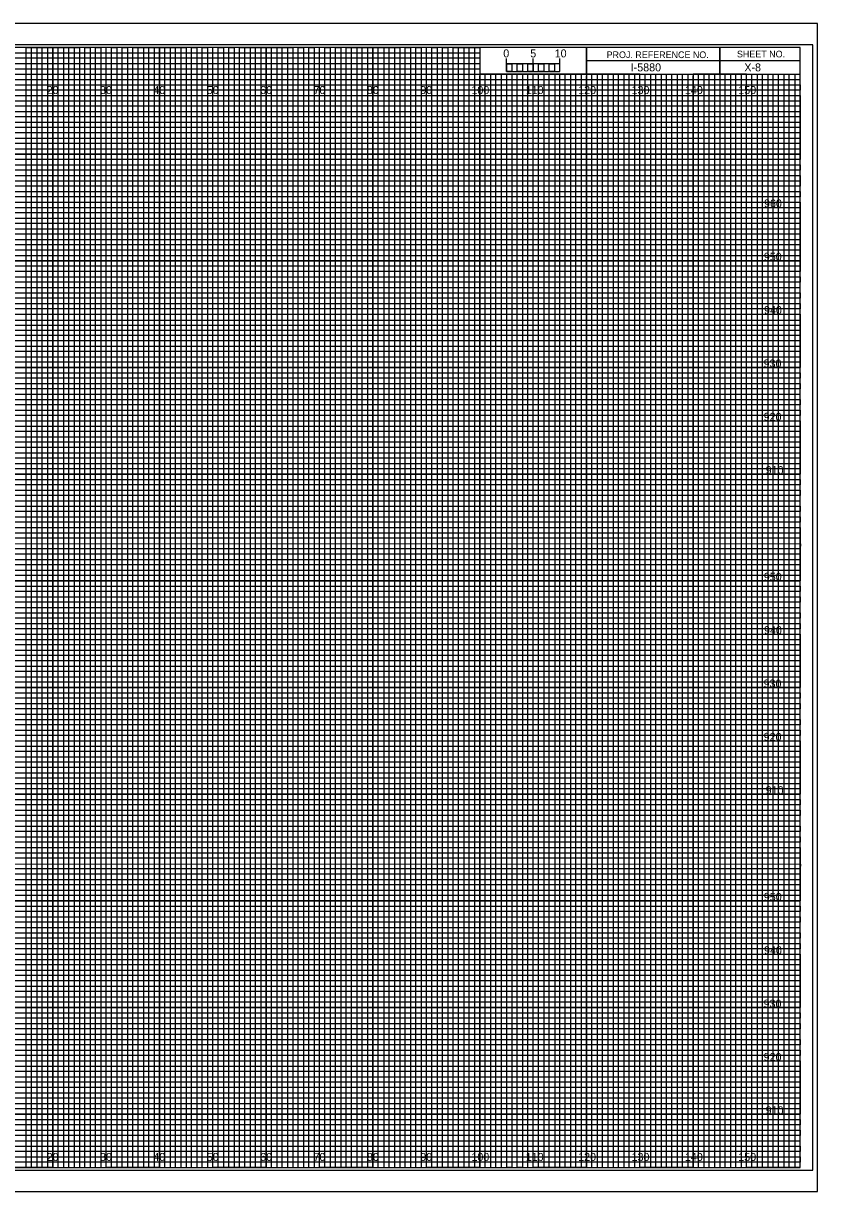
# Model space of a CAD drawing. Extents: x -13 to 323, y -4 to 3074.
# Drawn here: x 174.5 to 323.3, y 1315.5 to 1534.5 of the extents above; entities that cross this region are included whole.
import ezdxf

# ---------------------------------------------------------------- set-up
doc = ezdxf.new("R2010")
doc.units = 0
for name, color, linetype in [('Prop XS Bar Scale Labels', 7, 'Continuous'), ('Prop XS Elevation Labels', 7, 'Continuous'), ('Prop XS Offset Labels', 7, 'Continuous'), ('Prop XS Project Number', 7, 'Continuous'), ('Prop XS Sheet Number', 7, 'Continuous'), ('Sheet Cross Section CELL', 7, 'Continuous'), ('Sheet Cross Section Grid Major CELL', 7, 'Continuous'), ('Sheet Cross Section Grid Middle CELL', 7, 'Continuous'), ('Sheet Cross Section Grid Minor 1 CELL', 7, 'Continuous'), ('Sheet Cross Section Grid Minor 2 CELL', 7, 'Continuous'), ('Sheet Cross Section Scale CELL', 7, 'Continuous'), ('Sheet Cutting Line CELL', 7, 'Continuous'), ('Sheet DOT Grid CELL', 7, 'Continuous'), ('Sheet Plot Border Inside CELL', 7, 'Continuous'), ('Sheet Plot Border Outside CELL', 7, 'Continuous')]:
    doc.layers.add(name, color=color, linetype=linetype)

msp = doc.modelspace()

# ---------------------------------------------------------------- linework, layer by layer
at = {"layer": 'Sheet Cross Section CELL'}
for p, q in [((305, 1530), (305, 1525)), ((305, 1525), (305, 1530)), ((280, 1527.5), (280, 1525)), ((320, 1527.49), (280, 1527.49)), ((280, 1525), (320, 1525))]:
    msp.add_line(p, q, dxfattribs=at)
for points in [[(320, 1530), (0, 1530), (0, 1320), (320, 1320)], [(280, 1530), (260, 1530), (260, 1525.03), (280, 1525.03)], [(320, 1530), (280, 1530), (280, 1525), (320, 1525)]]:
    msp.add_lwpolyline(points, close=True, dxfattribs=at)
at = {"layer": 'Sheet Cross Section Grid Major CELL'}
for p, q in [((190, 1530), (180, 1530)), ((180, 1530), (180, 1320)), ((190, 1320), (190, 1530)), ((210, 1530), (200, 1530)), ((200, 1530), (200, 1320)), ((210, 1320), (210, 1530)), ((230, 1530), (220, 1530)), ((220, 1530), (220, 1320)), ((230, 1320), (230, 1530)), ((250, 1530), (240, 1530)), ((240, 1530), (240, 1320)), ((250, 1320), (250, 1530)), ((260, 1530), (260, 1320)), ((270, 1320), (270, 1525)), ((290, 1525), (280, 1525)), ((280, 1525), (280, 1320)), ((290, 1320), (290, 1525)), ((310, 1525), (300, 1525)), ((300, 1525), (300, 1320)), ((310, 1320), (310, 1525)), ((180, 1320), (170, 1320)), ((200, 1320), (190, 1320)), ((220, 1320), (210, 1320)), ((240, 1320), (230, 1320)), ((260, 1320), (250, 1320)), ((280, 1320), (270, 1320)), ((300, 1320), (290, 1320)), ((320, 1320), (310, 1320)), ((320, 1320), (320, 1320))]:
    msp.add_line(p, q, dxfattribs=at)
for points in [[(0, 1520), (320, 1520), (320, 1510), (0, 1510)], [(0, 1500), (320, 1500), (320, 1490), (0, 1490)], [(0, 1480), (320, 1480), (320, 1470), (0, 1470)], [(0, 1460), (320, 1460), (320, 1450), (0, 1450)], [(0, 1440), (320, 1440), (320, 1430), (0, 1430)], [(0, 1420), (320, 1420), (320, 1410), (0, 1410)], [(0, 1400), (320, 1400), (320, 1390), (0, 1390)], [(0, 1380), (320, 1380), (320, 1370), (0, 1370)], [(0, 1360), (320, 1360), (320, 1350), (0, 1350)], [(0, 1340), (320, 1340), (320, 1330), (0, 1330)]]:
    msp.add_lwpolyline(points, dxfattribs=at)
at = {"layer": 'Sheet Cross Section Grid Middle CELL'}
for points in [[(165, 1320), (175, 1320), (175, 1530), (185, 1530), (185, 1320), (195, 1320), (195, 1530), (205, 1530), (205, 1320), (215, 1320), (215, 1530), (225, 1530), (225, 1320), (235, 1320), (235, 1530), (245, 1530), (245, 1320), (255, 1320), (255, 1530), (259.93, 1530), (260, 1530), (260, 1525), (264.99, 1525), (264.99, 1320), (275, 1320), (275, 1525), (285, 1525), (285, 1320), (295, 1320), (295, 1525), (305, 1525), (305, 1320), (315, 1320), (315, 1525)], [(0, 1525), (275, 1525)], [(0, 1505), (320, 1505), (320, 1515), (0, 1515)], [(0, 1485), (320, 1485), (320, 1495), (0, 1495)], [(0, 1465), (320, 1465), (320, 1475), (0, 1475)], [(0, 1445), (320, 1445), (320, 1455), (0, 1455)], [(0, 1425), (320, 1425), (320, 1435), (0, 1435)], [(0, 1405), (320, 1405), (320, 1415), (0, 1415)], [(0, 1385), (320, 1385), (320, 1395), (0, 1395)], [(0, 1365), (320, 1365), (320, 1375), (0, 1375)], [(0, 1345), (320, 1345), (320, 1355), (0, 1355)], [(0, 1325), (320, 1325), (320, 1335), (0, 1335)]]:
    msp.add_lwpolyline(points, dxfattribs=at)
at = {"layer": 'Sheet Cross Section Grid Minor 1 CELL'}
for p, q in [((0, 1529), (260, 1529)), ((260, 1529), (260, 1527.98)), ((260, 1527.98), (0, 1527.98)), ((0, 1527), (260, 1527)), ((260, 1527), (260, 1525.89)), ((260, 1525.89), (0, 1525.89)), ((0, 1524), (320, 1524))]:
    msp.add_line(p, q, dxfattribs=at)
for points in [[(0, 1523), (270, 1523), (320, 1523), (320, 1522), (0, 1522)], [(0, 1521), (320, 1521), (320, 1519), (0, 1519)], [(0, 1518), (320, 1518), (320, 1517), (0, 1516.98)], [(0, 1516), (320, 1516), (320, 1514), (0, 1514)], [(0, 1513), (320, 1513), (320, 1512), (0, 1512)], [(0, 1511), (320, 1511), (320, 1509), (0, 1509)], [(0, 1508), (320, 1508), (320, 1507), (0, 1507)], [(0, 1506), (320, 1506), (320, 1504), (0, 1504)], [(0, 1503), (320, 1503), (320, 1502), (0, 1502)], [(0, 1501), (320, 1501), (320, 1499), (0, 1499)], [(0, 1498), (320, 1498), (320, 1497), (0, 1497)], [(0, 1496), (320, 1496), (320, 1493.95), (320, 1493), (320, 1492), (0, 1492)], [(0, 1494), (320, 1494), (320, 1493), (0, 1493)], [(0, 1491), (320, 1491), (320, 1489), (0, 1489.03)], [(0, 1489.03), (320, 1489), (320, 1488), (0, 1488)], [(0, 1487), (320, 1487), (320, 1486), (0, 1486)], [(0, 1484), (320, 1484), (320, 1483), (0, 1483)], [(0, 1482), (320, 1482), (320, 1481), (0, 1481)], [(-0.07, 1478.89), (320, 1478.89), (320, 1477.88), (-0.07, 1477.88)], [(0, 1477), (320, 1477), (320, 1476), (0, 1476)], [(0, 1474), (320, 1474), (320, 1473), (0, 1473)], [(0, 1472), (320, 1472), (320, 1471), (0, 1471)], [(0, 1469), (320, 1469), (320, 1468), (0, 1468)], [(0, 1467), (320, 1467), (320, 1466), (0, 1466)], [(0, 1464), (320, 1464), (320, 1463), (0, 1463)], [(0, 1462), (320, 1462), (320, 1461), (0, 1461)], [(0, 1459), (320, 1459), (319.99, 1457.98), (0, 1458)], [(0, 1457), (320, 1457), (320, 1456), (0, 1456)], [(0, 1454), (320, 1454), (320, 1453), (0, 1453)], [(0, 1452), (320, 1452), (320, 1451), (0, 1451)], [(0, 1449), (320, 1449), (320, 1448), (0, 1448)], [(0, 1447), (320, 1447), (320, 1446), (0, 1446)], [(0, 1444), (320, 1444), (320, 1443), (0, 1443)], [(0, 1442), (320, 1442), (320, 1441), (0, 1441)], [(0, 1439), (320, 1439), (320, 1438), (0, 1438)], [(0, 1436.99), (320.07, 1436.91), (320, 1436), (0, 1436)], [(0, 1434), (320, 1434), (320, 1433), (0, 1433)], [(0, 1432), (320, 1432), (320, 1431), (0, 1431)], [(0, 1429), (320, 1429), (320, 1428), (0, 1428)], [(0, 1427), (320, 1427), (320, 1426), (0, 1426)], [(0, 1424), (320, 1424), (320, 1423), (0, 1423)], [(0, 1422), (320, 1422), (320, 1421), (0, 1421)], [(0, 1419), (320, 1419), (320, 1418), (0, 1418)], [(0, 1417), (320, 1417), (320, 1416), (0, 1416)], [(0, 1414), (320, 1414), (320, 1413), (0, 1413)], [(0, 1412), (320, 1412), (320, 1411), (0, 1411)], [(0, 1409), (320, 1409), (320, 1408), (0, 1408)], [(0, 1407), (320, 1407), (320, 1406), (0, 1406)], [(0, 1404), (320, 1404), (320, 1403), (0, 1403)], [(0, 1402), (320, 1402), (320, 1401), (0, 1401)], [(0, 1399), (320, 1399), (319.99, 1397.98), (0, 1398)], [(0, 1397), (320, 1397), (320, 1396), (0, 1396)], [(0, 1394), (320, 1394), (320, 1393), (0, 1393)], [(0, 1392), (320, 1392), (320, 1391), (0, 1391)], [(0, 1389), (320, 1389), (320, 1388), (0, 1388)], [(0, 1387), (320, 1387), (320, 1386), (0, 1386)], [(0, 1384), (320, 1384), (320, 1383), (0, 1383)], [(0, 1382), (320, 1382), (320, 1381), (0, 1381)], [(0, 1379), (320, 1379), (320, 1378), (0, 1378)], [(0, 1376.99), (320.07, 1376.91), (320, 1376), (0, 1376)], [(0, 1374), (320, 1374), (320, 1373), (0, 1373)], [(0, 1372), (320, 1372), (320, 1371), (0, 1371)], [(0, 1369), (320, 1369), (320, 1368), (0, 1368)], [(0, 1367), (320, 1367), (320, 1366), (0, 1366)], [(0, 1364), (320, 1364), (320, 1363), (0, 1363)], [(0, 1362), (320, 1362), (320, 1361), (0, 1361)], [(0, 1359), (320, 1359), (320, 1358), (0, 1358)], [(0, 1357), (320, 1357), (320, 1356), (0, 1356)], [(0, 1354), (320, 1354), (320, 1353), (0, 1353)], [(0, 1352), (320, 1352), (320, 1351), (0, 1351)], [(0, 1349), (320, 1349), (320, 1348), (0, 1348)], [(0, 1347), (320, 1347), (320, 1346), (0, 1346)], [(0, 1344), (320, 1344), (320, 1343), (0, 1343)], [(0, 1342), (320, 1342), (320, 1341), (0, 1341)], [(0, 1339), (320, 1339), (320, 1338), (0, 1338)], [(0, 1337), (320, 1337), (320, 1336), (0, 1336)], [(0, 1334), (320, 1334), (320, 1333), (0, 1333)], [(0, 1332), (320, 1332), (320, 1331), (0, 1331)], [(0, 1329), (320, 1329), (320, 1328), (0, 1328)], [(0, 1327), (320, 1327), (320, 1326), (0, 1326)], [(0, 1324), (320, 1324), (320, 1323), (0, 1323)], [(0, 1322), (320, 1322), (320, 1321), (0, 1321)]]:
    msp.add_lwpolyline(points, dxfattribs=at)
at = {"layer": 'Sheet Cross Section Grid Minor 2 CELL'}
for p, q in [((267, 1525), (266.01, 1525)), ((266.01, 1525), (266.01, 1320)), ((267, 1320), (267, 1525)), ((269, 1525), (268, 1525)), ((268, 1525), (268, 1320)), ((269, 1320), (269, 1525)), ((266.01, 1320), (265, 1320)), ((268, 1320), (267, 1320))]:
    msp.add_line(p, q, dxfattribs=at)
for points in [[(175, 1320), (176, 1320), (176, 1530), (177, 1530), (177, 1320)], [(177, 1320), (178, 1320), (178, 1530), (179, 1530), (179, 1320)], [(180, 1320), (181, 1320), (181, 1530), (182, 1530), (182, 1320)], [(182, 1320), (183, 1320), (183, 1530), (184, 1530), (184, 1320)], [(185, 1320), (186, 1320), (186, 1530), (187, 1530), (187, 1320)], [(187, 1320), (188, 1320), (188, 1530), (189, 1530), (189, 1320)], [(190, 1320), (191, 1320), (191, 1530), (192, 1530), (192, 1320)], [(192, 1320), (193, 1320), (193, 1530), (194, 1530), (194, 1320)], [(195, 1320), (196, 1320), (196, 1530), (197, 1530), (197, 1320)], [(197, 1320), (198, 1320), (198, 1530), (199, 1530), (199, 1320)], [(200, 1320), (201, 1320), (201, 1530), (202, 1530), (202, 1320)], [(202, 1320), (203, 1320), (203, 1530), (204, 1530), (204, 1320)], [(205, 1320), (206, 1320), (206, 1530), (207, 1530), (207, 1320)], [(207, 1320), (208, 1320), (208, 1530), (209, 1530), (209, 1320)], [(210, 1320), (211, 1320), (211, 1530), (212, 1530), (212, 1320)], [(212, 1320), (213, 1320), (213, 1530), (214, 1530), (214, 1320)], [(215, 1320), (216, 1320), (216, 1530), (217, 1530), (217, 1320)], [(217, 1320), (218, 1320), (218, 1530), (219, 1530), (219, 1320)], [(220, 1320), (221, 1320), (221, 1530), (222, 1530), (222, 1320)], [(222, 1320), (223, 1320), (223, 1530), (224, 1530), (224, 1320)], [(225, 1320), (226, 1320), (226, 1530), (227, 1530), (227, 1320)], [(227, 1320), (228, 1320), (228, 1530), (229, 1530), (229, 1320)], [(230, 1320), (231, 1320), (231, 1530), (232, 1530), (232, 1320)], [(232, 1320), (233, 1320), (233, 1530), (234, 1530), (234, 1320)], [(235, 1320), (236, 1320), (236, 1530), (237, 1530), (237, 1320)], [(237, 1320), (238, 1320), (238, 1530), (239, 1530), (239, 1320)], [(240, 1320), (241, 1320), (241, 1530), (242, 1530), (242, 1320)], [(242, 1320), (243, 1320), (243, 1530), (244, 1530), (244, 1320)], [(245, 1320), (246, 1320), (246, 1530), (247, 1530), (247, 1320)], [(247, 1320), (248, 1320), (248, 1530), (249, 1530), (249, 1320)], [(250, 1320), (251, 1320), (251, 1530), (252, 1530), (252, 1320)], [(252, 1320), (253, 1320), (253, 1530), (254, 1530), (254, 1320)], [(255, 1320), (256, 1320), (256, 1530), (257, 1530), (257, 1320)], [(257, 1320), (258, 1320), (258, 1530), (259, 1530), (259, 1320)], [(260, 1320), (261, 1320), (261, 1525), (262.02, 1525), (262.02, 1320)], [(262, 1320), (263, 1320), (263, 1525), (263.99, 1525), (263.99, 1320)], [(270, 1320), (270.98, 1320), (270.98, 1525), (272, 1525), (272, 1320)], [(272, 1320), (273, 1320), (273, 1525), (274.05, 1525), (274.05, 1320)], [(275, 1320), (276, 1320), (276, 1525), (277, 1525), (277, 1320)], [(277, 1320), (278, 1320), (278, 1525), (279, 1525), (279, 1320)], [(280, 1320), (281, 1320), (281, 1525), (282, 1525), (282, 1320)], [(282, 1320), (283, 1320), (283, 1525), (284, 1525), (284, 1320)], [(285, 1320), (286, 1320), (286, 1525), (287, 1525), (287, 1320)], [(287, 1320), (288, 1320), (288, 1525), (289, 1525), (289, 1320)], [(290, 1320), (291, 1320), (291, 1525), (292, 1525), (292, 1320)], [(292, 1320), (293, 1320), (293, 1525), (294, 1525), (294, 1320)], [(295, 1320), (296, 1320), (296, 1525), (297, 1525), (297, 1320)], [(297, 1320), (298, 1320), (298, 1525), (299, 1525), (299, 1320)], [(300, 1320), (301, 1320), (301, 1525), (302, 1525), (302, 1320)], [(302, 1320), (303, 1320), (303, 1525), (304, 1525), (304, 1320)], [(305, 1320), (306, 1320), (306, 1525), (307, 1525), (307, 1320)], [(307, 1320), (308, 1320), (308, 1525), (309, 1525), (309, 1320)], [(310, 1320), (311, 1320), (311, 1525), (312, 1525), (312, 1320)], [(312, 1320), (313, 1320), (313, 1525), (314, 1525), (314, 1320)], [(315, 1320), (316, 1320), (316, 1525), (317, 1525), (317, 1320)], [(317, 1320), (318, 1320), (318, 1525), (319, 1525), (319, 1320)]]:
    msp.add_lwpolyline(points, dxfattribs=at)
at = {"layer": 'Sheet Cross Section Scale CELL'}
for p, q in [((265, 1525.49), (265, 1527.9)), ((265, 1526.9), (265, 1527.9)), ((270, 1525.49), (270, 1527.9)), ((275, 1525.49), (275, 1527.9)), ((275, 1526.9), (275, 1527.9))]:
    msp.add_line(p, q, dxfattribs=at)
for points in [[(275, 1526.9), (265, 1526.9), (265, 1525.49), (275, 1525.49)], [(265, 1526.9), (266, 1526.9), (266, 1525.49), (265, 1525.49)], [(267, 1526.9), (268, 1526.9), (268, 1525.49), (267, 1525.49)], [(269, 1526.9), (270, 1526.9), (270, 1525.49), (269, 1525.49)], [(271, 1526.9), (272, 1526.9), (272, 1525.49), (271, 1525.49)], [(273, 1526.9), (274, 1526.9), (274, 1525.49), (273, 1525.49)]]:
    msp.add_lwpolyline(points, close=True, dxfattribs=at)
at = {"layer": 'Sheet Cutting Line CELL'}
for p, q in [((323.3, 1534.5), (-13.4, 1534.5)), ((-13.4, 1315.5), (323.3, 1315.5))]:
    msp.add_line(p, q, dxfattribs=at)
at = {"layer": 'Sheet DOT Grid CELL'}
for p, q in [((180, 1320), (180, 1530)), ((190, 1320), (190, 1530)), ((200, 1320), (200, 1530)), ((210, 1320), (210, 1530)), ((220, 1320), (220, 1530)), ((230, 1320), (230, 1530)), ((240, 1320), (240, 1530)), ((250, 1320), (250, 1530)), ((260, 1320), (260, 1524.69)), ((270, 1320), (270, 1524.69)), ((280, 1320), (280, 1524.69)), ((290, 1320), (290, 1524.69)), ((300, 1320), (300, 1524.69)), ((310, 1320), (310, 1524.69)), ((0, 1520), (320, 1520)), ((0, 1510), (320, 1510)), ((0, 1500), (320, 1500)), ((0, 1490), (320, 1490)), ((0, 1480), (320, 1480)), ((0, 1470), (320, 1470)), ((0, 1460), (320, 1460)), ((0, 1450), (320, 1450)), ((0, 1440), (320, 1440)), ((0, 1430), (320, 1430)), ((0, 1420), (320, 1420)), ((0, 1410), (320, 1410)), ((0, 1400), (320, 1400)), ((0, 1390), (320, 1390)), ((0, 1380), (320, 1380)), ((0, 1370), (320, 1370)), ((0, 1360), (320, 1360)), ((0, 1350), (320, 1350)), ((0, 1340), (320, 1340)), ((0, 1330), (320, 1330))]:
    msp.add_line(p, q, dxfattribs=at)
at = {"layer": 'Sheet Plot Border Inside CELL'}
msp.add_lwpolyline([(-10.8, 1319.5), (322.4, 1319.5), (322.4, 1530.5), (-10.8, 1530.5)], close=True, dxfattribs=at)
at = {"layer": 'Sheet Plot Border Outside CELL'}
msp.add_lwpolyline([(-13.4, 1315.5), (323.3, 1315.5), (323.3, 1534.5), (-13.4, 1534.5)], close=True, dxfattribs=at)

# ---------------------------------------------------------------- texts
at = {"layer": 'Prop XS Bar Scale Labels'}
for s, p in [('5', (269.47, 1528.12)), ('10', (274.04, 1528.12))]:
    msp.add_text(s, height=1.5, dxfattribs=at).set_placement(p)
at = {"layer": 'Prop XS Elevation Labels'}
for s, p in [('960', (313.26, 1500)), ('950', (313.22, 1490)), ('940', (313.26, 1480)), ('930', (313.18, 1470)), ('920', (313.19, 1460)), ('910', (313.57, 1450)), ('950', (313.22, 1430)), ('940', (313.26, 1420)), ('930', (313.18, 1410)), ('920', (313.19, 1400)), ('910', (313.57, 1390)), ('950', (313.22, 1370)), ('940', (313.26, 1360)), ('930', (313.18, 1350)), ('920', (313.19, 1340)), ('910', (313.57, 1330))]:
    msp.add_text(s, height=1.5, dxfattribs=at).set_placement(p)
at = {"layer": 'Prop XS Offset Labels'}
for s, p in [('20', (178.86, 1521.25)), ('30', (188.86, 1521.25)), ('40', (198.86, 1521.25)), ('50', (208.86, 1521.25)), ('60', (218.86, 1521.25)), ('70', (228.86, 1521.25)), ('80', (238.86, 1521.25)), ('90', (248.86, 1521.25)), ('100', (258.44, 1521.25)), ('110', (268.62, 1521.25)), ('120', (278.44, 1521.25)), ('130', (288.44, 1521.25)), ('140', (298.44, 1521.25)), ('150', (308.44, 1521.25)), ('20', (178.86, 1321.25)), ('30', (188.86, 1321.25)), ('40', (198.86, 1321.25)), ('50', (208.86, 1321.25)), ('60', (218.86, 1321.25)), ('70', (228.86, 1321.25)), ('80', (238.86, 1321.25)), ('90', (248.86, 1321.25)), ('100', (258.44, 1321.25)), ('110', (268.62, 1321.25)), ('120', (278.44, 1321.25)), ('130', (288.44, 1321.25)), ('140', (298.44, 1321.25)), ('150', (308.44, 1321.25))]:
    msp.add_text(s, height=1.5, dxfattribs=at).set_placement(p)
at = {"layer": 'Prop XS Project Number'}
msp.add_text('I-5880', height=1.5, dxfattribs=at).set_placement((288.28, 1525.5))
at = {"layer": 'Prop XS Sheet Number'}
msp.add_text('X-8', height=1.5, dxfattribs=at).set_placement((309.57, 1525.5))
at = {"layer": 'Sheet Cross Section CELL'}
for s, p in [('PROJ. REFERENCE NO.', (283.77, 1527.99)), ('SHEET NO.', (308.19, 1528.12))]:
    msp.add_text(s, height=1.25, dxfattribs=at).set_placement(p)
at = {"layer": 'Sheet Cross Section Scale CELL'}
msp.add_text('0', height=1.5, dxfattribs=at).set_placement((264.41, 1528.12))

doc.saveas('drawing.dxf')
